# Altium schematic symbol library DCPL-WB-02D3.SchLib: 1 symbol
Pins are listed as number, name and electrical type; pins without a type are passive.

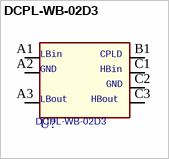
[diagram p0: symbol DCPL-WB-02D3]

## DCPL-WB-02D3
designator U?
footprint ST_CSP07N51P3X3_167X144X63
pins: A1 LBin, A2 GND, A3 LBout, B1 CPLD, C1 HBin, C2 GND1, C3 HBout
